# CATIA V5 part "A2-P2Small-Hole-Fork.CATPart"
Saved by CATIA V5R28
Part number: Small-Hole-Fork-Base
Revision: ANY
Definition: UNKNOWN
Nomenclature: Small-Hole-Fork-Base
Source: Unknown
Bounding box of the stored display mesh (mm): x 0 to 142, y -36 to 36, z -36 to 36
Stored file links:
  E:\TP Catia - Documents\Additional Exercise\Contrôle\Problem-3-Section-J\A2-P2Small-Hole-Fork.CATPart
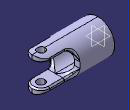
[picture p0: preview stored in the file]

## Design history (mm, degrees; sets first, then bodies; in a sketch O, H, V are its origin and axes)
Body1 "Imported1" (main body)
  Solid1: solid without history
